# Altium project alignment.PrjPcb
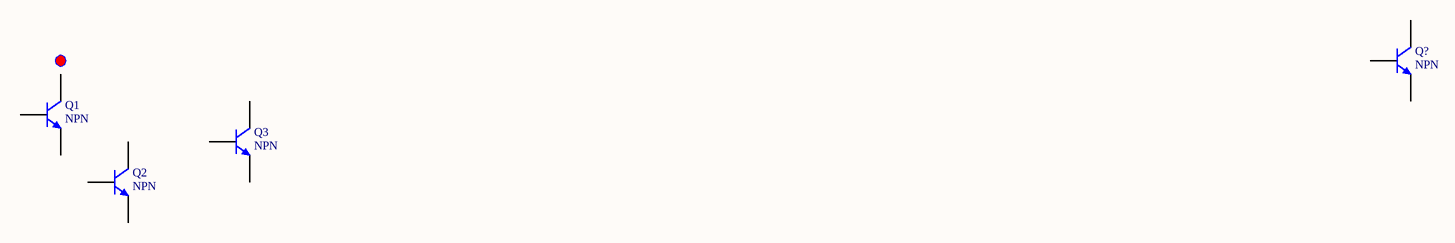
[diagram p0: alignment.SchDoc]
3 sheets, 10 parts. Net scope: global (net labels, ports and power ports of the same name join across sheets).
Sheets:
  alignment.SchDoc
  alignment1.SchDoc
  alignment2.SchDoc

## Sheet alignment.SchDoc
size A4

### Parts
(Parts that share a designator on the sheet are numbered #1, #2 ... from top to bottom, then left to right.)
Q1#1  NPN  [BCY-W3]
Q2#1  NPN  [BCY-W3]
Q3#1  NPN  [BCY-W3]
Q?  NPN  [BCY-W3]

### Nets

Not connected (* = marked no-connect by the designer): Q1#1 1(C) 2(B) 3(E); Q2#1 1(C) 2(B) 3(E); Q3#1 1(C) 2(B) 3(E); Q? 1(C) 2(B) 3(E)

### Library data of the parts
Q1#1 Q2#1 Q3#1 Q? = NPN: NPN Bipolar Transistor

## Sheet alignment1.SchDoc
size A4
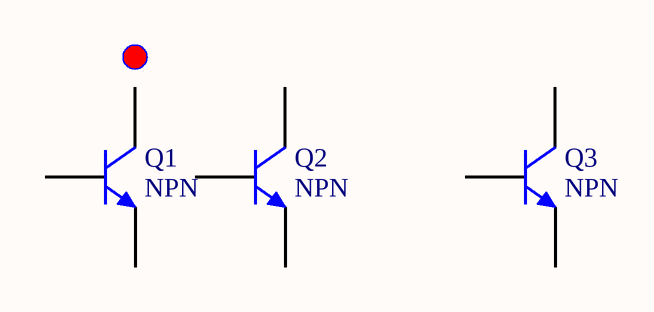
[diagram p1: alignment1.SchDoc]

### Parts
(Parts that share a designator on the sheet are numbered #1, #2 ... from top to bottom, then left to right.)
Q1#2  NPN  [BCY-W3]
Q2#2  NPN  [BCY-W3]
Q3#2  NPN  [BCY-W3]

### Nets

Not connected (* = marked no-connect by the designer): Q1#2 1(C) 2(B) 3(E); Q2#2 1(C) 2(B) 3(E); Q3#2 1(C) 2(B) 3(E)

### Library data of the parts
Q1#2 Q2#2 Q3#2 = NPN: NPN Bipolar Transistor

## Sheet alignment2.SchDoc
size A4
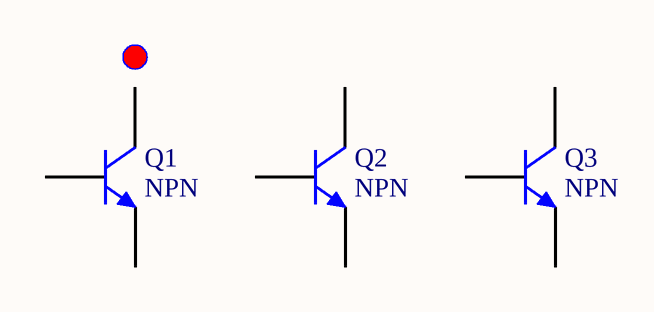
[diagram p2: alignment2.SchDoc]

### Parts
(Parts that share a designator on the sheet are numbered #1, #2 ... from top to bottom, then left to right.)
Q1#3  NPN  [BCY-W3]
Q2#3  NPN  [BCY-W3]
Q3#3  NPN  [BCY-W3]

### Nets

Not connected (* = marked no-connect by the designer): Q1#3 1(C) 2(B) 3(E); Q2#3 1(C) 2(B) 3(E); Q3#3 1(C) 2(B) 3(E)

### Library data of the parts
Q1#3 Q2#3 Q3#3 = NPN: NPN Bipolar Transistor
